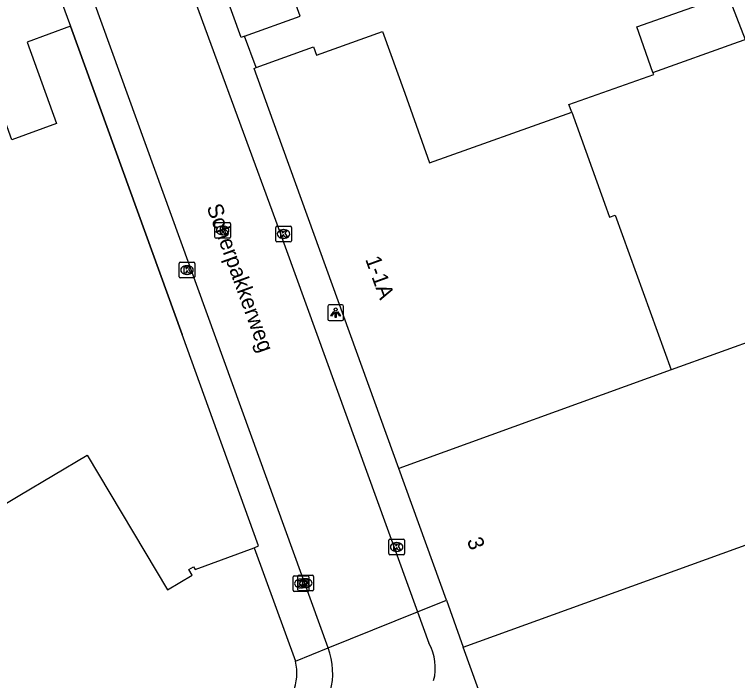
# Model space of a CAD drawing. Extents: x 159503 to 160347, y 382525 to 383272.
# Drawn here: x 159705.48 to 159751.59, y 383061.72 to 383104.2 of the extents above; entities that cross this region are included whole.
import ezdxf

# ---------------------------------------------------------------- set-up
doc = ezdxf.new("R2010")
doc.units = 0
for name, color, linetype in [('IMGEO_Kolk', 7, 'Continuous'), ('IMGEO_Lichtpunt', 7, 'Continuous'), ('IMGEO_Muur', 7, 'Continuous'), ('IMGEO_Openbare_ruimte_label', 7, 'Continuous'), ('IMGEO_Pand', 7, 'Continuous'), ('IMGEO_Pand_nummerreeks', 7, 'Continuous'), ('IMGEO_Rijbaan_lokaal_open', 7, 'Continuous'), ('IMGEO_Rioolput', 7, 'Continuous'), ('IMGEO_Voetpad_open', 7, 'Continuous')]:
    doc.layers.add(name, color=color, linetype=linetype)

msp = doc.modelspace()

# ---------------------------------------------------------------- linework, layer by layer
at = {"layer": 'IMGEO_Kolk'}
for p, q in [((159722.137, 383089.771), (159722.137, 383090.623)), ((159722.212, 383090.697), (159723.064, 383090.697)), ((159722.625, 383090.477), (159722.65, 383090.477)), ((159723.138, 383090.623), (159723.138, 383089.771)), ((159722.648, 383089.917), (159722.623, 383089.917)), ((159723.064, 383089.697), (159722.212, 383089.697)), ((159715.981, 383087.471), (159715.981, 383088.323)), ((159716.056, 383088.397), (159716.908, 383088.397)), ((159716.469, 383088.177), (159716.494, 383088.177)), ((159716.982, 383088.323), (159716.982, 383087.471)), ((159716.492, 383087.617), (159716.467, 383087.617)), ((159716.908, 383087.397), (159716.056, 383087.397)), ((159729.351, 383069.813), (159729.351, 383070.665)), ((159729.426, 383070.739), (159730.278, 383070.739)), ((159729.839, 383070.519), (159729.864, 383070.519)), ((159730.352, 383070.665), (159730.352, 383069.813)), ((159730.278, 383069.739), (159729.426, 383069.739)), ((159729.862, 383069.959), (159729.837, 383069.959)), ((159723.243, 383067.483), (159723.243, 383068.335)), ((159723.318, 383068.409), (159724.17, 383068.409)), ((159723.553, 383067.51), (159723.553, 383068.362)), ((159723.628, 383068.436), (159724.48, 383068.436)), ((159723.731, 383068.189), (159723.756, 383068.189)), ((159724.041, 383068.216), (159724.066, 383068.216)), ((159724.244, 383068.335), (159724.244, 383067.483)), ((159724.554, 383068.362), (159724.554, 383067.51)), ((159724.17, 383067.409), (159723.318, 383067.409)), ((159724.48, 383067.436), (159723.628, 383067.436)), ((159723.754, 383067.629), (159723.729, 383067.629)), ((159724.064, 383067.656), (159724.039, 383067.656))]:
    msp.add_line(p, q, dxfattribs=at)
for points in [[(159722.137, 383089.771), (159722.137, 383090.623)], [(159722.212, 383090.697), (159723.064, 383090.697)], [(159722.458, 383090.397), (159722.581, 383090.397), (159722.581, 383090.246), (159722.711, 383090.397), (159722.875, 383090.397), (159722.729, 383090.246), (159722.882, 383089.997), (159722.73, 383089.997), (159722.645, 383090.161), (159722.581, 383090.094), (159722.581, 383089.997), (159722.458, 383089.997), (159722.458, 383090.397)], [(159723.138, 383090.623), (159723.138, 383089.771)], [(159723.064, 383089.697), (159722.212, 383089.697)], [(159715.981, 383087.471), (159715.981, 383088.323)], [(159716.056, 383088.397), (159716.908, 383088.397)], [(159716.302, 383088.097), (159716.425, 383088.097), (159716.425, 383087.946), (159716.555, 383088.097), (159716.719, 383088.097), (159716.573, 383087.946), (159716.726, 383087.697), (159716.574, 383087.697), (159716.489, 383087.861), (159716.425, 383087.794), (159716.425, 383087.697), (159716.302, 383087.697), (159716.302, 383088.097)], [(159716.982, 383088.323), (159716.982, 383087.471)], [(159716.908, 383087.397), (159716.056, 383087.397)], [(159729.351, 383069.813), (159729.351, 383070.665)], [(159729.426, 383070.739), (159730.278, 383070.739)], [(159729.672, 383070.439), (159729.795, 383070.439), (159729.795, 383070.288), (159729.925, 383070.439), (159730.089, 383070.439), (159729.943, 383070.288), (159730.096, 383070.039), (159729.944, 383070.039), (159729.859, 383070.203), (159729.795, 383070.136), (159729.795, 383070.039), (159729.672, 383070.039), (159729.672, 383070.439)], [(159730.352, 383070.665), (159730.352, 383069.813)], [(159730.278, 383069.739), (159729.426, 383069.739)], [(159723.243, 383067.483), (159723.243, 383068.335)], [(159723.318, 383068.409), (159724.17, 383068.409)], [(159723.553, 383067.51), (159723.553, 383068.362)], [(159723.628, 383068.436), (159724.48, 383068.436)], [(159723.874, 383068.136), (159723.997, 383068.136), (159723.997, 383067.985), (159724.127, 383068.136), (159724.291, 383068.136), (159724.145, 383067.985), (159724.298, 383067.736), (159724.146, 383067.736), (159724.061, 383067.9), (159723.997, 383067.833), (159723.997, 383067.736), (159723.874, 383067.736), (159723.874, 383068.136)], [(159724.244, 383068.335), (159724.244, 383067.483)], [(159724.554, 383068.362), (159724.554, 383067.51)], [(159723.564, 383068.109), (159723.687, 383068.109), (159723.687, 383067.958), (159723.817, 383068.109), (159723.981, 383068.109), (159723.835, 383067.958), (159723.988, 383067.709), (159723.836, 383067.709), (159723.751, 383067.873), (159723.687, 383067.806), (159723.687, 383067.709), (159723.564, 383067.709), (159723.564, 383068.109)], [(159724.17, 383067.409), (159723.318, 383067.409)], [(159724.48, 383067.436), (159723.628, 383067.436)]]:
    msp.add_lwpolyline(points, dxfattribs=at)
for centre, start, end in [((159722.214, 383090.621), 91.552, 178.448), ((159722.214, 383090.621), 91.552, 178.448), ((159723.062, 383090.621), 1.552, 88.448), ((159723.062, 383090.621), 1.552, 88.448), ((159722.214, 383089.773), 181.552, 268.448), ((159722.214, 383089.773), 181.552, 268.448), ((159723.062, 383089.773), 271.552, 358.448), ((159723.062, 383089.773), 271.552, 358.448), ((159716.058, 383088.321), 91.552, 178.448), ((159716.058, 383088.321), 91.552, 178.448), ((159716.906, 383088.321), 1.552, 88.448), ((159716.906, 383088.321), 1.552, 88.448), ((159716.058, 383087.473), 181.552, 268.448), ((159716.058, 383087.473), 181.552, 268.448), ((159716.906, 383087.473), 271.552, 358.448), ((159716.906, 383087.473), 271.552, 358.448), ((159729.428, 383070.663), 91.552, 178.448), ((159729.428, 383070.663), 91.552, 178.448), ((159730.276, 383070.663), 1.552, 88.448), ((159730.276, 383070.663), 1.552, 88.448), ((159729.428, 383069.815), 181.552, 268.448), ((159729.428, 383069.815), 181.552, 268.448), ((159730.276, 383069.815), 271.552, 358.448), ((159730.276, 383069.815), 271.552, 358.448), ((159723.32, 383068.333), 91.552, 178.448), ((159723.32, 383068.333), 91.552, 178.448), ((159723.63, 383068.36), 91.552, 178.448), ((159723.63, 383068.36), 91.552, 178.448), ((159724.168, 383068.333), 1.552, 88.448), ((159724.168, 383068.333), 1.552, 88.448), ((159724.478, 383068.36), 1.552, 88.448), ((159724.478, 383068.36), 1.552, 88.448), ((159723.32, 383067.485), 181.552, 268.448), ((159723.32, 383067.485), 181.552, 268.448), ((159723.63, 383067.512), 181.552, 268.448), ((159723.63, 383067.512), 181.552, 268.448), ((159724.168, 383067.485), 271.552, 358.448), ((159724.168, 383067.485), 271.552, 358.448), ((159724.478, 383067.512), 271.552, 358.448), ((159724.478, 383067.512), 271.552, 358.448)]:
    msp.add_arc(centre, 0.0765, start, end, dxfattribs=at)
for centre, major_axis, ratio, start_param, end_param in [((159722.624, 383090.197), (-0.387, 0.002), 0.722429, 4.712389, 7.853982), ((159722.649, 383090.197), (-0.39, 0.002), 0.717154, 1.570796, 4.712389), ((159716.468, 383087.897), (-0.387, 0.002), 0.722429, 4.712389, 7.853982), ((159716.493, 383087.897), (-0.39, 0.002), 0.717154, 1.570796, 4.712389), ((159729.838, 383070.239), (-0.387, 0.002), 0.722429, 4.712389, 7.853982), ((159729.863, 383070.239), (-0.39, 0.002), 0.717154, 1.570796, 4.712389), ((159723.73, 383067.909), (-0.387, 0.002), 0.722429, 4.712389, 7.853982), ((159724.04, 383067.936), (-0.387, 0.002), 0.722429, 4.712389, 7.853982), ((159723.755, 383067.909), (-0.39, 0.002), 0.717154, 1.570796, 4.712389), ((159724.065, 383067.936), (-0.39, 0.002), 0.717154, 1.570796, 4.712389)]:
    msp.add_ellipse(centre, major_axis=major_axis, ratio=ratio, start_param=start_param, end_param=end_param, dxfattribs=at)
at = {"layer": 'IMGEO_Lichtpunt'}
for p, q in [((159726.366, 383085.678), (159725.558, 383085.678)), ((159726.366, 383085.678), (159725.558, 383085.678)), ((159725.464, 383085.583), (159725.464, 383084.776)), ((159725.464, 383085.583), (159725.464, 383084.776)), ((159726.46, 383084.776), (159726.46, 383085.583)), ((159726.46, 383084.776), (159726.46, 383085.583)), ((159725.558, 383084.682), (159726.366, 383084.682)), ((159725.558, 383084.682), (159726.366, 383084.682))]:
    msp.add_line(p, q, dxfattribs=at)
for points in [[(159725.838, 383085.247), (159725.877, 383085.219), (159725.689, 383084.957), (159725.651, 383084.984), (159725.838, 383085.247)], [(159725.94, 383085.199), (159725.987, 383085.199), (159725.987, 383084.877), (159725.94, 383084.877), (159725.94, 383085.199)], [(159726.05, 383085.219), (159726.088, 383085.246), (159726.275, 383084.984), (159726.236, 383084.956), (159726.05, 383085.219)]]:
    msp.add_lwpolyline(points, dxfattribs=at)
msp.add_circle((159725.963, 383085.381), 0.0994, dxfattribs=at)
for centre, start, end in [((159725.558, 383085.583), 90, 180), ((159725.558, 383085.583), 90, 180), ((159726.366, 383085.583), 0, 90), ((159726.366, 383085.583), 0, 90), ((159725.558, 383084.776), 180, 270), ((159725.558, 383084.776), 180, 270), ((159726.366, 383084.776), 270, 0), ((159726.366, 383084.776), 270, 360)]:
    msp.add_arc(centre, 0.0946, start, end, dxfattribs=at)
at = {"layer": 'IMGEO_Muur'}
msp.add_lwpolyline([(159709.062, 383103.442), (159716.163, 383083.785)], dxfattribs=at)
at = {"layer": 'IMGEO_Pand'}
for points in [[(159720.154, 383102.805), (159719.926, 383102.723), (159715.764, 383114.25)], [(159720.154, 383102.805), (159723.69, 383104.081), (159721.905, 383109.03), (159726.139, 383110.557), (159726.349, 383110.633)], [(159706.469, 383110.478), (159709.062, 383103.442)], [(159746.195, 383100.496), (159745.163, 383103.411), (159750.673, 383105.363), (159750.969, 383105.468), (159752.065, 383102.601)], [(159709.062, 383103.442), (159706.281, 383102.431), (159708.167, 383097.243), (159705.301, 383096.202), (159703.388, 383101.469), (159703.199, 383101.4), (159702.725, 383102.575)], [(159720.883, 383100.808), (159724.554, 383102.135), (159724.75, 383101.593), (159728.952, 383103.113), (159730.37, 383099.172), (159731.94, 383094.743), (159741.014, 383097.958)], [(159746.195, 383100.496), (159751.654, 383102.454), (159752.065, 383102.601)], [(159729.981, 383075.247), (159722.255, 383096.618), (159720.757, 383100.762), (159720.883, 383100.808)], [(159741.014, 383097.958), (159740.84, 383098.448), (159746.243, 383100.362), (159746.195, 383100.496)], [(159741.014, 383097.958), (159743.22, 383091.858), (159743.43, 383091.278), (159743.787, 383091.407), (159747.357, 383081.526)], [(159756.226, 383084.731), (159747.357, 383081.526)], [(159747.357, 383081.526), (159729.981, 383075.247)], [(159690.956, 383064.681), (159705.824, 383073.54), (159710.119, 383076.099), (159715.241, 383067.503), (159716.82, 383068.444), (159716.606, 383068.804), (159716.894, 383068.975), (159716.994, 383068.806), (159720.757, 383070.183)], [(159733.021, 383066.837), (159729.981, 383075.247)], [(159734.103, 383063.845), (159760.373, 383073.343)], [(159720.757, 383070.183), (159723.403, 383062.952)], [(159733.021, 383066.837), (159734.103, 383063.845)], [(159737.559, 383054.283), (159734.103, 383063.845)]]:
    msp.add_lwpolyline(points, dxfattribs=at)
msp.add_arc((159720.134, 383062.196), 3.356, 304.2878, 13.0138, dxfattribs=at)
at = {"layer": 'IMGEO_Rijbaan_lokaal_open'}
for points in [[(159713.868, 383113.551), (159722.133, 383091.085), (159731.176, 383066.11)], [(159725.487, 383063.808), (159708.326, 383111.163)], [(159725.487, 383063.808), (159731.176, 383066.11)], [(159731.176, 383066.11), (159731.906, 383064.095)]]:
    msp.add_lwpolyline(points, dxfattribs=at)
for centre, radius, start, end in [((159729.181, 383062.54), 3.138, 344.8895, 29.7111), ((159721.044, 383062.184), 4.73, 311.9285, 20.0777)]:
    msp.add_arc(centre, radius, start, end, dxfattribs=at)
at = {"layer": 'IMGEO_Rioolput'}
for p, q in [((159718.257, 383090.002), (159718.257, 383090.854)), ((159718.332, 383090.928), (159719.184, 383090.928)), ((159719.258, 383090.854), (159719.258, 383090.002)), ((159718.745, 383090.708), (159718.77, 383090.708)), ((159719.184, 383089.928), (159718.332, 383089.928)), ((159718.768, 383090.148), (159718.743, 383090.148))]:
    msp.add_line(p, q, dxfattribs=at)
for points in [[(159718.257, 383090.002), (159718.257, 383090.854)], [(159718.332, 383090.928), (159719.184, 383090.928)], [(159719.258, 383090.854), (159719.258, 383090.002)], [(159718.846, 383090.626), (159718.594, 383090.628), (159718.594, 383090.228)], [(159718.594, 383090.228), (159718.718, 383090.228), (159718.718, 383090.39), (159718.729, 383090.39)], [(159718.772, 383090.547), (159718.718, 383090.547), (159718.718, 383090.466)], [(159718.718, 383090.466), (159718.77, 383090.466)], [(159718.776, 383090.361), (159718.847, 383090.228), (159718.987, 383090.228), (159718.922, 383090.354)], [(159719.184, 383089.928), (159718.332, 383089.928)]]:
    msp.add_lwpolyline(points, dxfattribs=at)
for centre, radius, start, end in [((159718.334, 383090.852), 0.0765, 91.552, 178.448), ((159718.334, 383090.852), 0.0765, 91.552, 178.448), ((159719.182, 383090.852), 0.0765, 1.552, 88.448), ((159719.182, 383090.852), 0.0765, 1.552, 88.448), ((159718.728, 383090.337), 0.0533, 26.0293, 88.6989), ((159718.754, 383090.655), 0.19, 274.7715, 282.9687), ((159718.778, 383090.451), 0.0964, 77.0061, 93.1865), ((159718.792, 383090.508), 0.0378, 276.6634, 79.6772), ((159718.845, 383090.516), 0.109, 350.3612, 89.416), ((159718.843, 383090.516), 0.112, 277.5842, 350.9817), ((159718.827, 383090.301), 0.108, 29.5134, 73.7905), ((159718.334, 383090.004), 0.0765, 181.552, 268.448), ((159718.334, 383090.004), 0.0765, 181.552, 268.448), ((159719.182, 383090.004), 0.0765, 271.552, 358.448), ((159719.182, 383090.004), 0.0765, 271.552, 358.448)]:
    msp.add_arc(centre, radius, start, end, dxfattribs=at)
for centre, major_axis, ratio, start_param, end_param in [((159718.744, 383090.428), (-0.387, 0.002), 0.722429, 4.712389, 7.853982), ((159718.769, 383090.428), (-0.39, 0.002), 0.717154, 1.570796, 4.712389)]:
    msp.add_ellipse(centre, major_axis=major_axis, ratio=ratio, start_param=start_param, end_param=end_param, dxfattribs=at)
at = {"layer": 'IMGEO_Voetpad_open'}
for points in [[(159720.757, 383070.183), (159721.034, 383070.303), (159716.163, 383083.785), (159709.062, 383103.442)], [(159720.883, 383100.808), (159720.154, 383102.805)], [(159731.176, 383066.11), (159733.021, 383066.837)], [(159723.403, 383062.952), (159725.487, 383063.808)]]:
    msp.add_lwpolyline(points, dxfattribs=at)

# ---------------------------------------------------------------- texts
at = {"layer": 'IMGEO_Openbare_ruimte_label'}
msp.add_text('Scherpakkerweg', height=1, rotation=289.939, dxfattribs=at).set_placement((159717.717, 383091.922))
at = {"layer": 'IMGEO_Pand_nummerreeks'}
for s, p in [('1-1A', (159727.834, 383088.594)), ('3', (159734.317, 383070.661))]:
    msp.add_text(s, height=1, rotation=289.8757, dxfattribs=at).set_placement(p)

doc.saveas('drawing.dxf')
